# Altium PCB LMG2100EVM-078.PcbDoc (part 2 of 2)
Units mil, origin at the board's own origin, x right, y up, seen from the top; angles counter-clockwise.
Board outline 2400 x 2700 mil, 4 copper layers (Top Layer, MidLayer1, MidLayer2, Bottom Layer), stack 61.2 mil thick; 76 components, 27 nets, 153 pads, 244 vias.
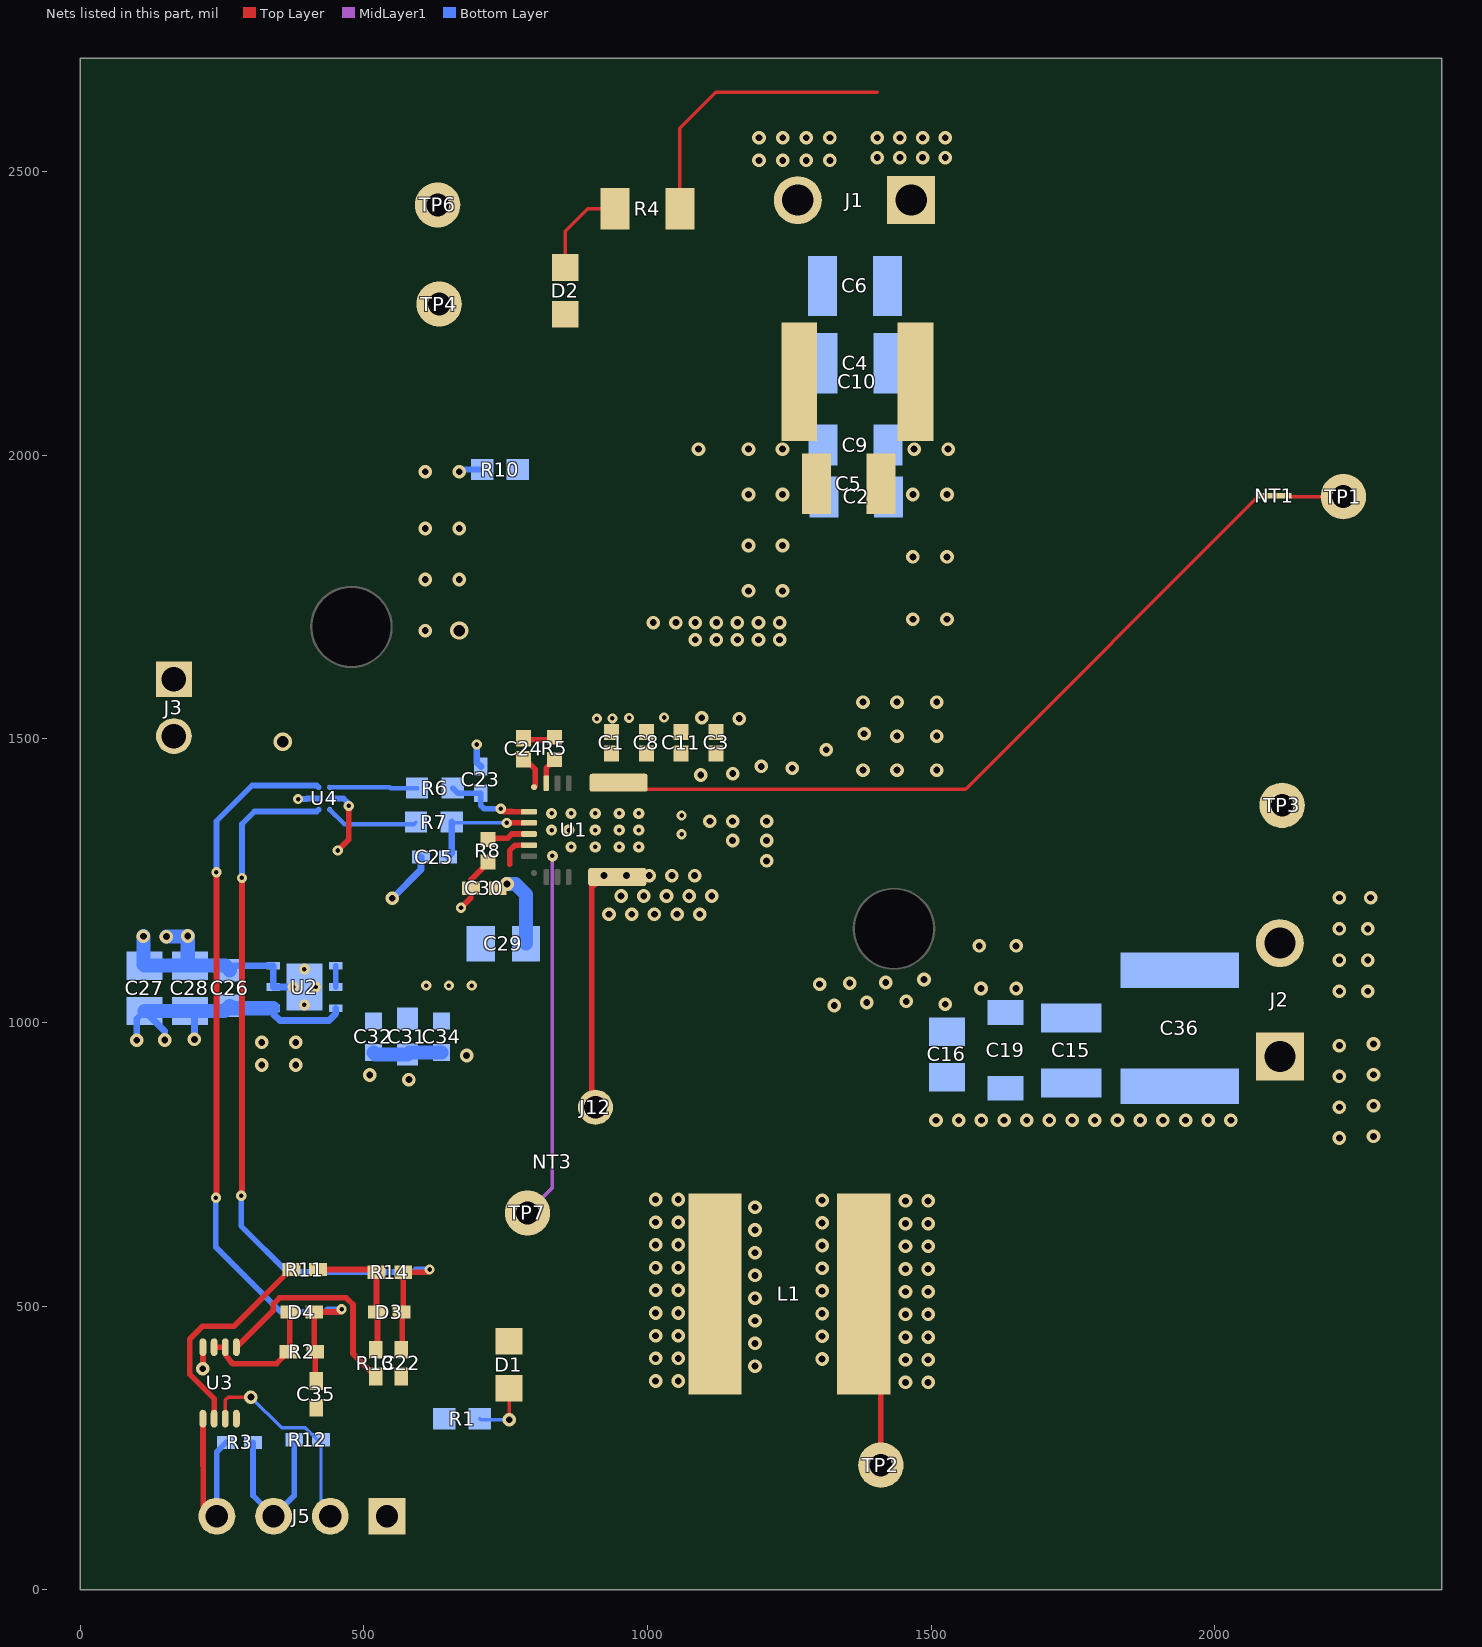
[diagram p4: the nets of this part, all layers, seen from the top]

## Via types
v1: diameter 24, hole 12, Top Layer to Bottom Layer, tented both sides, 201 vias
v2: diameter 19.68, hole 7.87, Top Layer to Bottom Layer, tented both sides, 15 vias
v3: diameter 18, hole 8, Top Layer to Bottom Layer, tented both sides, 13 vias
v4: diameter 18, hole 8, Top Layer to Bottom Layer, 9 vias
v5: diameter 19.68, hole 7.87, Top Layer to Bottom Layer, 4 vias
v6: diameter 32, hole 20, Top Layer to Bottom Layer, 2 vias

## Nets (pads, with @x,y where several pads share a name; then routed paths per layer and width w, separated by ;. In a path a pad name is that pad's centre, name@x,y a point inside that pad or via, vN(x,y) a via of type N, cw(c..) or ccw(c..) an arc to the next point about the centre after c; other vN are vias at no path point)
5V: C29.2 C30.1 C31.2 C32.1 C34.1 R1.1 R8.1 TP6.1 U2.4 U2.5 U3.8 U4.B2 | length 301.9
  Top Layer w10: v1(215.72,389.52) 216.22,390.02 U3.8@216.19,427.51 ; v4(454,1303.27) 473.23,1322.5 v4(473.23,1381.98) ; v4(671.17,1202.35) 688.67,1219.84 C30.1@688.67,1236.5 688.67,1251.62 R8.1@718.44,1281.39
  Bottom Layer w10: U4.B2@439.84,1395 455.09,1395 464,1395 473.23,1385.77 v4(473.23,1381.98) ; U2.5@450.24,1062.6 U2.4@450.24,1100
  other v3: 610,1065 650,1065 690,1065
EXT_VCC: C26.1 C27.2 C28.2 J3.1 U2.1 U2.6 | length 548.5
  Bottom Layer w12: v1(99.52,968.75) 99.52,1006.62 C27.2@113.2,1020.3 149.02,984.48 v1(149.02,969.25) ; C28.2@193.2,1020.3 201.14,1012.36 v1(201.14,970.31) ; U2.1@340,1025.2 340,1015.31 351.91,1003.4 438.33,1003.4 450.24,1015.31 U2.6@450.24,1025.2
  Bottom Layer w25: C27.2@113.2,1020.3 C28.2@193.2,1020.3 254.39,1020.3 C26.1@263.4,1029.31 267.51,1025.2 U2.1@340,1025.2
GND: C22.2 C23.1 C25.2 C26.2 C27.1 C28.1 C29.1 C30.2 C31.1 C32.2 C34.2 C35.2 D1.2 J3.2 J5.1 J5.3 R3.2 R10.2 R12.1 TP4.1 U1.15 U2.2 U2.3 U2.7 U3.4 U4.B1 | length 1268.7
  Top Layer w10: C30.2@734.73,1237.69 C30.2@735.91,1236.5 ; 757,1279 757,1303 766.64,1312.64 U1.15@791.14,1312.64
  Bottom Layer w10: R3.2@304.34,259.52 304.34,165.89 J5.3@340.72,129.52 377.1,165.89 R12.1@377.1,264.52 ; v3@390,1393.99 398.99,1393.99 400,1395 U4.B1@420.1,1395 ; v1(668,1971) 672,1975 R10.2@708.5,1975
  Bottom Layer w12: C26.2@263.4,1092.3 271.1,1100 U2.3@340,1100 U2.2@340,1062.6 v5(375.43,1062.6) ; v1(550,1219) 600.8,1269.8 C25.2@600.8,1291.8 ; v3(699,1490.2) 699,1458.6 C23.1@706.2,1451.4
  Bottom Layer w25: v1(111.2,1152.1) 111.2,1102.3 C27.1@113.2,1100.3 C28.1@193.2,1100.3 ; v1(151.8,1151.5) 188.3,1151.5 v1(189.4,1152.6) 189.4,1104.1 C28.1@193.2,1100.3 ; C26.2@263.4,1092.3 255.4,1100.3 C28.1@193.2,1100.3 ; C32.2@516.85,947 520.35,943.5 C31.1@576.78,943.5 580.28,947 C34.2@636.85,947 ; v1(752.32,1244.31) 767.22,1244.31 785.84,1225.7 C29.1@785.84,1139.06
  other v1: 579.4,899.4 510.4,907.4 320,925 380,925 681,941.8 320,965 380,965 608,1691 608,1781 668,1781 608,1871 668,1871 608,1971
  other v3: 383.86,1393.99
  other v5: 395.12,1031.1 414.8,1062.6 395.12,1094.1
  other v6: 357,1495 668,1691
HI_SIGNAL: R6.2 U4.C2 | length 154.5
  Bottom Layer w6: 545.53,1414.69 546.43,1413.78
  Bottom Layer w8: U4.C2@439.84,1414.69 545.53,1414.69 ; 546.43,1413.78 546.91,1413.3 R6.2@593.7,1413.3
K_VIN: NT1.2 TP1.1 | length 105.5
  Top Layer w6: NT1.2@2121.5,1927.26 TP1.1@2226.98,1927.26
K_VIN_GND: NT3.1 TP7.1 | length 98.5
  MidLayer1 w6: TP7.1@788.43,664.18 832.43,708.18 NT3.1@832.43,744.41
LO_SIGNAL: R7.2 U4.A2 | length 164
  Bottom Layer w6: R7.2@588.3,1349.9 R7.2@591.8,1353.4
  Bottom Layer w8: U4.A2@439.84,1375.32 465.26,1349.9 547,1349.9 R7.2@588.3,1349.9
NetC22_1: C22.1 D3.1 R14.2 U4.A1 | length 1408.9
  Top Layer w10: v4(283.6,694.4) 285,695.8 v4(285,1255) ; C22.1@565.72,423.14 567.37,424.79 567.37,489.52 569.34,491.48 R14.2@569.34,559.52 610.72,559.52 v3(615.72,564.52)
  Bottom Layer w10: v4(283.6,694.4) 283.6,641.2 364.8,560 586.72,560 591.23,564.52 v3(615.72,564.52) ; v4(285,1255) 285,1350 307,1372 416.8,1372 U4.A1@420.1,1375.3
NetC23_2: C23.2 R6.1 U1.12 | length 164.3
  Top Layer w10: v4(741.2,1376.8) 745.99,1372.01 759.98,1372.01 760.3,1371.69 U1.12@791.14,1371.69
  Bottom Layer w10: R6.1@656.7,1413.3 665.84,1404.16 C23.2@706.2,1404.16 706.2,1382.66 712.06,1376.8 v4(741.2,1376.8)
NetC24_1: C24.1 R5.1 | length 54.4
  Top Layer w10: C24.1@781.5,1498.65 835.32,1498.65 R5.1@835.7,1499.03
NetC24_2: C24.2 U1.11 | length 61.4
  Top Layer w10: C24.2@781.5,1467.15 801.97,1446.68 801.97,1416.97 U1.11@800,1415
NetC25_1: C25.1 R7.1 U1.13 | length 201.3
  Top Layer w10: v4(751.7,1352.01) U1.13@791.14,1352.01
  Bottom Layer w6: R7.1@654.8,1353.4 656.19,1352.01 v4(751.7,1352.01)
  Bottom Layer w12: C25.1@648.04,1291.8 654.8,1298.55 R7.1@654.8,1353.4
NetC35_1: C35.1 D4.1 R2.2 U4.C1 | length 1403.1
  Top Layer w10: v4(239,691.2) 240,692.2 v4(240,1265) ; C35.1@415.72,368.14 414.34,369.52 R2.2@414.34,419.52 412.37,421.48 D4.1@412.37,489.52 455.72,489.52 v3(460.72,494.52)
  Bottom Layer w10: v4(239,691.2) 239,603.8 352.8,490 431.72,490 436.23,494.52 v3(460.72,494.52) ; v4(240,1265) 240,1355 303,1418 416.8,1418 U4.C1@420.1,1414.7
NetD1_1: D1.1 R1.2 | length 108.1
  Top Layer w6: v1(756.16,299.57) D1.1@756.16,355.18
  Bottom Layer w6: R1.2@704.51,301.49 706.43,299.57 v1(756.16,299.57)
NetD2_1: D2.1 R4.2 | length 168.1
  Top Layer w6: D2.1@855,2331.34 855,2395 895,2435 R4.2@942.91,2435
NetD3_2: D3.2 R11.1 R13.2 R14.1 | length 243.4
  Top Layer w10: R11.1@419.34,564.52 517.09,564.52 R14.1@522.09,559.52 522.09,491.48 524.06,489.52 524.06,426.48 R13.2@520.72,423.14
NetD4_2: D4.2 R2.1 U3.6 U3.7 | length 217
  Top Layer w10: U3.7@235.87,427.51 U3.6@255.56,427.51 ; U3.6@256.72,413.52 268.28,398.52 346.1,398.52 R2.1@367.1,419.52 369.06,421.48 D4.2@369.06,489.52
NetJ5_2: J5.2 R12.2 U3.3 | length 371.6
  Top Layer w6: U3.3@255.56,301.52 255.62,334.42 260.72,339.52 v1@295.72,339.52
  Bottom Layer w6: v1(300.72,339.52) 354.91,285.33 396.57,285.33 417.38,264.52 R12.2@424.34,264.52 424.34,145.89 J5.2@440.72,129.52
NetJ5_4: J5.4 R3.1 U3.1 | length 307.8
  Top Layer w10: U3.1@216.19,301.52 J5.4@216.72,130.52
  Bottom Layer w10: J5.4@240.72,129.52 240.72,243.14 R3.1@257.1,259.52
NetR5_2: R5.2 U1.10 | length 51.6
  Top Layer w10: U1.10@821.65,1421.89 821.27,1422.27 821.27,1448.78 835.7,1463.21 R5.2@835.7,1467.37
NetR8_2: R8.2 U1.14 | length 75.9
  Top Layer w10: R8.2@718.44,1324.69 753.05,1324.69 760.68,1332.32 U1.14@791.14,1332.32
NetR11_2: R11.2 U3.2 | length 388.2
  Top Layer w10: U3.2@235.87,301.52 235.92,336.79 192.72,379.99 192.72,441.52 215.72,464.52 270.72,464.52 370.72,564.52 R11.2@372.09,564.52
NetR13_1: R13.1 U3.5 | length 396.5
  Top Layer w10: U3.5@275.24,427.51 340.35,492.55 340.35,503.91 350.95,514.52 469,514.52 480.72,502.8 480.72,415.89 R13.1@520.72,375.89
PGND: C1.2 C2.1 C3.2 C4.2 C5.2 C6.2 C8.2 C9.1 C10.1 C11.2 C15.2 C16.2 C19.2 C36.2 D2.2 J1.2 J2.2 NT3.2 R10.1 TP3.1 | length 533.4
  MidLayer1 w6: NT3.2@832.24,760.41 v2(832.24,1293.81)
  other v1: 1329.41,1029.99 1525.09,1032.07 1386.66,1035.19 1456.39,1037.27 2220,1055 2270,1055 1588,1060 1650,1060 1303.38,1067.45 1356.47,1069.54 1419.96,1070.59 1487.61,1075.78 2220,1110 2270,1110 1585,1135 1650,1135 2220,1165 2270,1165 2220,1220 2275,1220 1210,1285 1150,1321 1210,1321 1110,1355 1150,1355 1210,1355 1161.64,1535.87 1095.52,1537.33 1084.29,1675 1121.43,1675 1158.57,1675 1195.71,1675 1232.86,1675 1010,1705 1050,1705 1084.29,1705 1121.43,1705 1158.57,1705 1195.71,1705 1232.86,1705 1178,1761 1238,1761 1178,1841 1238,1841 1178,1931 1238,1931 1090,2011 1178,2011 1238,2011 1196.67,2520 1238.33,2520 1280,2520 1321.67,2520 1196.67,2560 1238.33,2560 1280,2560 1321.67,2560
  other v2: 865.24,1309.69 907.76,1309.69 950.28,1309.69 984.53,1309.69 830.98,1339.21 861.3,1339.21 907.76,1339.21 950.28,1339.21 984.53,1339.21 830.98,1368.74 865.24,1368.74 907.76,1368.74 950.28,1368.74 984.53,1368.74
  other v3: 1060,1332 1060,1365 910.75,1535.87 938.15,1536.09 967.66,1537.12 1029.19,1537.75
SW: J12.1 L1.1 U1.5 | length 420.2
  Top Layer w10: J12.1@908.28,850.57 901.5,857.35 901.5,1237.45 v1(923.1,1259.05)
  other v1: 1014.27,367.87 1054.27,367.87 1189.51,394.17 1014.27,407.87 1054.27,407.87 1189.51,434.17 1014.27,447.87 1054.27,447.87 1189.51,474.17 1014.27,487.87 1054.27,487.87 1189.51,514.17 1014.27,527.87 1054.27,527.87 1189.51,554.17 1014.27,567.87 1054.27,567.87 1189.51,594.17 1014.27,607.87 1054.27,607.87 1189.51,634.17 1014.27,647.87 1054.27,647.87 1189.51,674.17 1014.27,687.87 1054.27,687.87 932.15,1190.96 972.15,1190.96 1012.15,1190.96 1052.15,1190.96 1092.15,1190.96 953.44,1223 993.44,1223 1033.44,1223 1073.44,1223 1113.44,1223 963.1,1259.05 1003.1,1259.05 1043.1,1259.05 1083.1,1259.05
VIN: C1.1 C2.2 C3.1 C4.1 C5.1 C6.1 C8.1 C9.2 C10.2 C11.1 J1.1 NT1.1 R4.1 U1.7 | length 1876.1
  Top Layer w6: U1.7@949.09,1422.87 960.55,1411.42 1560.77,1411.42 2078.03,1928.68 NT1.1@2090.18,1928.68 ; R4.1@1057.09,2435 1057.09,2577.09 1120,2640 1405,2640
  other v1: 1093.81,1436.35 1150.37,1438.77 1380,1445 1440,1445 1510,1445 1255.16,1448.46 1200.71,1451.61 1315.15,1481.06 1440,1505 1510,1505 1382,1509 1380,1565 1440,1565 1510,1565 1468,1711 1528,1711 1468,1821 1528,1821 1468,1931 1528,1931 1470,2011 1530,2011 1405,2525 1445,2525 1485,2525 1525,2525 1405,2560 1445,2560 1485,2560 1525,2560
VOUT: C15.1 C16.1 C19.1 C36.1 J2.1 L1.2 TP2.1 | length 314.5
  Top Layer w6: L1.2@1381.31,521.62 L1.2@1411.4,491.53
  Top Layer w10: TP2.1@1411.4,219.57 L1.2@1411.4,491.53
  other v1: 1454.84,365.41 1494.84,365.41 1454.84,405.41 1494.84,405.41 1307.84,406.76 1454.84,445.41 1494.84,445.41 1307.84,446.76 1454.84,485.41 1494.84,485.41 1307.84,486.76 1454.84,525.42 1494.84,525.42 1307.84,526.76 1454.84,565.42 1494.84,565.42 1307.84,566.76 1454.84,605.42 1494.84,605.42 1307.84,606.76 1454.84,645.42 1494.84,645.42 1307.84,646.76 1454.84,685.42 1494.84,685.42 1307.84,686.76 2220,796.43 2280,799.29 1508.69,827.54 1548.69,827.54 1588.69,827.54 1628.69,827.54 1668.69,827.54 1708.69,827.54 1748.69,827.54 1788.69,827.54 1828.69,827.54 1868.69,827.54 1908.69,827.54 1948.69,827.54 1988.69,827.54 2028.69,827.54 2220,850.71 2280,853.57 2220,905 2280,907.86 2220,959.29 2280,962.14
pads on no net: H9.0 H10.0 H11.0 H12.0 U1.1 U1.2 U1.3 U1.4 U1.8 U1.9 U1.16

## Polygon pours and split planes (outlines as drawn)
5V on Bottom Layer "Bottom Layer-5V" (solid, pour order 63): 50,50 819.39,50 850.65,89.61 850.65,1053.22 809.27,1104.61 789.6,1104.61 804.95,1376.99 710,1463 710,2635 690,2655 50,2655 50,1028.36 50,655
PGND on Bottom Layer "Bottom Layer-No Net 8" (solid, pour order 45): 751.68,2389.2 976.97,2655.22 1341.72,2655.22 1360,2636.95 1360,1651.84 1213.12,1513.24 892.29,1513.24 751.68,1655.67
VOUT on Bottom Layer "Bottom Layer-No Net 4" (solid, pour order 64): 2350,968.17 2350,392.64 2280.19,322.83 1336.28,322.83 1280.33,378.79 1280.33,925 1836.05,925 1906.05,995 2323.16,995
SW on Bottom Layer "NONET_L-01_P-001" (solid, pour order 65): 1094.12,1273.09 1247.18,1120.03 1247.18,324.05 1205.62,282.48 941.27,282.48 896,327.75 896,786.81 951.77,827.13 951.77,882.52 896,922.02 896,1265.04 904.05,1273.08
PGND on Bottom Layer "Bottom Layer-PGND" (solid, pour order 62): 1291.09,1273.29 1306.56,1230.5 1290.55,1214.48 1290.59,1114.41 1290.55,1114.37 1290.55,950.04 1290.59,950 1290.6,950.01 1290.61,950 1807,950 1892,1035 2320,1035 2350,1065 2350,1715 1908,1715 1581,1380.59 1234.45,1380.59 1234.15,1378.55 1222.89,1378.55 820.7,1378.55 820.67,1378.58 816.4,1374.31 816.4,1295.66 820.78,1291.28 1177.2,1291.28 1195.19,1273.29
VIN on Bottom Layer "Bottom Layer-No Net 7" (solid, pour order 43): 1410,2655 1930,2655 1960,2626.17 1960,1799.67 1549.5,1408.41 897.22,1408.41 897.22,1438.4 897.22,1484.1 919.02,1484.1 1241.36,1484.1 1385.49,1628.22 1385.97,2630.97
GND on Bottom Layer "GND_L04_P031" (solid, pour order 31): 487.72,961.74 487.72,898.35 499.68,886.4 706.4,886.4 706.4,886.7 710.4,890.7 709.8,891.3 709.8,966.4 699.87,976.33 502.31,976.33 490.71,964.73
GND on Bottom Layer "Top Layer-No Net 7" (solid, pour order 42): 497.92,931.06 497.92,957.52 506.53,966.13 648.73,966.13 655.55,959.31 655.55,927.1 503.65,927.1
GND on MidLayer1 "MidLayer1-No Net 2" (solid, pour order 41): 793.92,97.97 752.39,50 68.89,50 48,70.88 48,2655 690,2655 710,2635 710,1464 774.17,1399.83 774.17,1283.7 793.92,1224.19
PGND on MidLayer1 "MidLayer1-No Net 1" (solid, pour order 60): 1336.25,322.81 1280.33,378.79 1280.33,1235.18 878.6,1235.18 843.4,1301.74 834.25,1307.58 821.16,1312.41 816.9,1316.67 816.9,1398.1 740.4,1476.96 740.4,2375.9 976.97,2655.22 2285.6,2655 2350,2596.65 2350,392.62 2280.19,322.81
SW on MidLayer1 "NONET_L-01_P-001" (solid, pour order 67): 1094.12,1273.09 1247.18,1120.03 1247.18,324.05 1205.62,282.48 941.27,282.48 896,327.75 896,786.81 951.77,827.13 951.77,882.52 896,922.02 896,1265.04 904.05,1273.08
EXT_VCC on MidLayer1 "EXT_VCC_L02_P036" (solid, pour order 36): 45.56,1667.98 51.35,1673.76 313.53,1673.76 335.25,1652.03 322.22,1639 322.22,1010.37 383.05,1010.37 395.45,997.97 404.18,949.52 412.13,905.43 412.13,839.11 395.45,822.43 383.05,804.68 380.38,807.35 68.74,804.68 34.31,839.11 34.31,1655.27 47,1667.97
GND on Top Layer "Top Layer-No Net 9" (solid, pour order 49): 33.04,1004.95 33.98,1005.89 33.98,1042.91 298.55,1042.91 301.31,1045.67 300.29,1046.68 300.29,1061.89 355.8,1061.89 365.2,1071.29 365.2,1101.97 425.04,1101.97 430.24,1096.77 430.24,1035.34 497.83,1035.34 555.25,1092.75 555.25,1104.61 695.55,1104.61 722.5,1077.66 830.17,1077.66 850.65,1053.22 850.65,89.61 819.39,50 33.04,50
PGND on Top Layer "Top Layer-No Net 2" (solid, pour order 27): 2350,1816.71 2007.3,1816.71 1569.18,1378.58 820.67,1378.58 816.68,1295.38 869.38,1299.51 870.48,1299.55 1103.1,1299.51 1290,1115 1290.59,1114.41 1290.59,950 1807,950 1892,1035 2350,1035 2320,1035 2350,1065
PGND on Top Layer "Top Layer-No Net 1" (solid, pour order 28): 751.68,2389.21 976.97,2655.22 1341.72,2655.22 1360,2636.51 1360,1651.84 1213.47,1513.25 892.11,1513.25 751.68,1656.09
SW on Top Layer "NONET_L-01_P-001" (solid, pour order 66): 1094.12,1273.09 1247.18,1120.03 1247.18,324.05 1205.62,282.48 941.27,282.48 896,327.75 896,786.81 951.77,827.13 951.77,882.52 920.11,904.94 920.11,1239.58 904.05,1273.08
VOUT on Top Layer "Bottom Layer-No Net 4" (solid, pour order 70): 2350,968.17 2350,392.64 2280.19,322.83 1336.28,322.83 1280.33,378.79 1280.33,925 1836.05,925 1906.05,995 2323.16,995
GND on Top Layer "Top Layer-No Net 10" (solid, pour order 32): 30,1065 289.13,1065 309.13,1085 309.13,1088.33 448.99,1088.33 489.82,1129.16 489.82,1174.82 500,1185 775.63,1185 792.26,1201.64 790.51,1378.58 712,1463 710,1463 710,2635 690,2655 30,2655
EXT_VCC on Top Layer "Top Layer-No Net 8" (solid, remove dead copper, pour order 50): 30,1065 289.13,1065 309.13,1088.33 340,1088.33 340,1100 350,1111.67 410,1111.67 420,1100 420,1088.33 450.87,1088.33 450,1089.34 450,1158.33 450,1170 420,1205 310,1205 300,1205 270,1240 180,1345 30,1345
5V on Top Layer "Top Layer-No Net 5" (solid, pour order 44): 420,1035.34 497.83,1035.34 500,1037.85 557.83,1105 560,1105 710,1105 720,1093.39 720,1081.78 720,1058.56 730,1046.95 730,1023.73 730,965.88 726.12,961.38 725.63,960.81 436.5,960.81
VIN on Top Layer "Top Layer-No Net" (solid, pour order 29): 1410,2655 1385.97,2630.97 1385.97,1628.22 1241.84,1484.1 897.22,1484.1 897.22,1479.74 897.22,1419.29 1552.41,1419.29 1960,1826.88 1960,2626.17 1930,2655
GND on MidLayer2 "AGND_PLANE" (solid, remove dead copper, pour order 55): 36,2651 40.04,2646.96 40.04,50 819.39,50 850.65,89.61 850.65,1223.27 804.95,1258.04 804.95,1376.99 712,1463 710,1465 710,2635 690,2655 48,2655
PGND on MidLayer2 "MidLayer1-No Net 1" (solid, pour order 71): 1336.25,322.81 1280.33,378.79 1280.33,1235.18 878.6,1235.18 816.9,1286.35 816.9,1398.1 740.4,1476.96 740.4,2375.9 976.97,2655.22 2285.6,2655 2350,2596.65 2350,392.62 2280.19,322.81
SW on MidLayer2 "NONET_L-01_P-001" (solid, pour order 68): 1094.12,1273.09 1247.18,1120.03 1247.18,324.05 1205.62,282.48 941.27,282.48 896,327.75 896,786.81 951.77,827.13 951.77,882.52 896,922.02 896,1265.04 904.05,1273.08
EXT_VCC on MidLayer2 "EXT_VCC_L03_P053" (solid, pour order 53): 29.19,1640.99 55.52,1667.32 55.52,1669.93 275.48,1669.93 304.14,1641.28 304.14,949.14 303.99,949.14 289.04,934.19 50.23,934.19 33.21,951.21 34.31,952.31 34.31,1652.28

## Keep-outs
Keep-Out Layer:
  text ".Layer_Name" at -323,-853.49 h60

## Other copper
Top Layer:
  text ".Layer_Name" at -323,-853.49 h60
Bottom Layer:
  text ".Layer_Name" at -323,-853.49 h60

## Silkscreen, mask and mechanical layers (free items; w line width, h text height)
Top Overlay:
  region: 2311,283 2000,283 2000,177 2311,177
  lines w10: 351.5,775.8 354,773.3 1709.2,773.3 1711.7,775.8 1711.7,1829.3 1706.6,1834.4 351.5,1834.4 351.5,775.8
  text "-" at 1045,2525 h80
  text "+" at 1615,2500 h80
  text "5V" at 476.43,2429.95 h40
  text "GND" at 452.99,2245.1 h40
  text "'.PRJ_Title'" at 96.77,2127.68 h42 r90
  text "Danger High" at 1579,2124 h72 r359.68
  text "Voltage" at 1716,2026 h72 r359.48
  text "GaN Evaluation Board" at 139,1902 h40
  text "VIN Sense+" at 1963,1808 h40
  text "EXTVCC" at 47.53,1780.05 h40
  text "5.5-10V" at 47.53,1718.52 h40
  text "GND" at 651,1719 h16
  text "GND" at 340,1523 h16
  text "GND" at 111.47,1381.88 h40
  text "PGND" at 1223,1374 h20
  text "-" at 2204.5,1253 h80 r90
  text "+" at 2134.2,744.6 h80
  text "VIN Sense-" at 340.77,679.62 h40
  text "IOUT 10A MAX" at 1794,588 h40
  text "Rev '.PCB_Rev'" at 2051,117 h40
  text "PWM I/P (HI)" at 824.49,79.44 h40 r90
  text "GND" at 874.53,79.17 h40 r90.25
  text "GND (LI)" at 930.73,78.79 h40 r90
  text "GND" at 988.77,79.42 h40 r90
  text "'.PRJ_Number'" at 1619.57,53.3 h40
  text ".Layer_Name" at -323,-853.49 h60
Bottom Overlay:
  text "UL 94V-0" at 2306,1647 h48
  text "Caution" at 2240.5,1562.1 h72 r359.68
  text "Hot Surface" at 2336.1,1466.5 h72 r359.68
  text ".Layer_Name" at -323,-853.49 h60
Top Paste:
  text ".Layer_Name" at -323,-853.49 h60
Bottom Paste:
  text ".Layer_Name" at -323,-853.49 h60
Top Solder:
  text ".Layer_Name" at -323,-853.49 h60
  text ".Layer_Name" at -323,-853.49 h60
Bottom Solder:
  text ".Layer_Name" at -323,-853.49 h60
Drill Guide:
  text ".Layer_Name" at -323,-853.49 h60
M1 Board Outline:
  lines w25: 5,0 5,2700 2400,2700 2400,0 5,0
  text ".Layer_Name" at -323,-853.49 h60
M2 Board Dimensions:
  rectangle: -775.5,-405.5 -400.5,-280.5
  rectangle: -900.5,-280.5 -775.5,-155.5
  lines w7: -900.5,-280.5 99.5,-280.5 ; -775.5,-405.5 -775.5,-155.5 ; -650.5,-405.5 -650.5,-155.5 ; -400.5,-405.5 -400.5,-155.5 ; -150.5,-405.5 -150.5,-155.5 ; -900.5,-405.5 -900.5,-155.5 99.5,-155.5 99.5,-405.5 -900.5,-405.5
  lines w10: -900.5,-470.5 -900.5,-450.5 ; -840.5,-480.5 -900.5,-460.5 ; -840.5,-440.5 -900.5,-460.5 ; -676.42,-460.5 -900.5,-460.5 ; -124.58,-460.5 99.5,-460.5 ; 39.5,-480.5 99.5,-460.5 ; 39.5,-440.5 99.5,-460.5 ; 99.5,-470.5 99.5,-450.5
  text "1000 (mil)" at -666.42,-496.49 h60
  text ".Layer_Name" at -323,-853.49 h60
M3 3D STEP Top:
  text ".Layer_Name" at -323,-853.49 h60
M4 3D STEP Bottom:
  text ".Layer_Name" at -323,-853.49 h60
M5 Assembly Top:
  lines w10: -1192,-925.17 5408,-925.17 ; -1192,-721.83 5410,-721.83 ; -1192,-518.5 -1192,-1128.5 2813,-1128.5 5410,-1128.5 5410,-518.5 -1191.5,-518.5 -1191.5,-1128.5 384,-1128.5 ; 1273,-1128.5 1273,-518.5 ; 2540,-721.83 2540,-518.5 ; 3380,-721.83 3380,-518.5 ; 4002,-1135 4002,-932.17
  text "COMPONENTS MARKED 'DNP' SHOULD NOT BE POPULATED." at 253.5,-313.5 h60
  text "ASSEMBLY VARIANT:" at 253,-429 h60
  text ".VariantName" at 1289,-429 h60
  text "PCB VIEWED FROM TOP SIDE" at -1128.5,-650.67 h60
  text "BOARD #:" at 1348,-650.67 h60
  text ".PRJ_Number" at 1893.5,-650.67 h60
  text "REV:" at 2738,-650.67 h60
  text ".PCB_Rev" at 3029.5,-650.67 h60
  text "SVN REV:" at 3576,-650.67 h60
  text ".VersionControl_RevNumber" at 4082,-650.67 h60
  text "IGNORE ->" at -1128.5,-853.49 h60
  text "PLOT NAME =" at -1128.5,-1059.33 h60
  text ".plot_File_Name" at -323,-1059.33 h60
  text "GENERATED    :" at 1350,-1059.33 h60
  text ".Print_Date" at 2219.5,-1059.33 h60
  text ".Print_Time" at 2948.5,-1059.33 h60
  text "TEXAS INSTRUMENTS" at 4213,-1059.33 h60
M6 Assembly Bottom:
  lines w10: -1192.5,-722.33 5409.5,-722.33 ; -1190.5,-925.67 5409.5,-925.67 ; 215.5,-1135.5 215.5,-932.67 ; 837.5,-722.33 837.5,-519 ; 1677.5,-722.33 1677.5,-519 ; 2944.5,-1129 2944.5,-519 ; 3833.5,-1129 5409,-1129 5409,-519 -1192.5,-519 -1192.5,-1129 1404.5,-1129 5409.5,-1129 5409.5,-519
  text "COMPONENTS MARKED 'DNP' SHOULD NOT BE POPULATED." at 5202,-313 h60
  text ".VariantName" at 4158,-429 h60
  text "ASSEMBLY VARIANT:" at 5197,-429 h60
  text ".VersionControl_RevNumber" at 135.5,-651.17 h60
  text "SVN REV:" at 641.5,-651.17 h60
  text ".PCB_Rev" at 1188,-651.17 h60
  text "REV:" at 1479.5,-651.17 h60
  text ".PRJ_Number" at 2324,-651.17 h60
  text "BOARD #:" at 2869.5,-651.17 h60
  text "PCB VIEWED FROM BOTTOM SIDE" at 5346,-651.17 h60
  text "IGNORE ->" at 1647.85,-853.49 h60
  text "TEXAS INSTRUMENTS" at 4.5,-1059.83 h60
  text ".Print_Time" at 1269,-1059.83 h60
  text ".Print_Date" at 1998,-1059.83 h60
  text "GENERATED    :" at 2867.5,-1059.83 h60
  text ".plot_File_Name" at 4540.5,-1059.83 h60
  text "PLOT NAME =" at 5346,-1059.83 h60
M9 Title Sheet:
  drawing of 56 lines, arcs and shapes, not listed
  text "1" at -160.16,8041.5 h70
  text "2" at 2335.5,8041.5 h70
  text "3" at 4824.84,8041.5 h70
  text "4" at 7331.51,8041.5 h70
  text "5" at 9830.5,8041.5 h70
  text "A" at -1316.5,6898.5 h70
  text "A" at 13483.5,6898.5 h70
  text "B" at -1316.5,4518.5 h70
  text "B" at 13483.5,4518.5 h70
  text "C" at -1316.5,2143.5 h70
  text "C" at 13483.5,2143.5 h70
  text "PROJECT TITLE:" at 10443.5,282.5 h45
  text ".PRJ_Title" at 10493.5,149.17 h70
  text "DESIGNED FOR:" at 10443.5,-18.5 h45
  text ".PRJ_Customer" at 10493.5,-158.5 h70
  text "D" at -1316.5,-226.5 h70
  text "D" at 13483.5,-226.5 h70
  text "FILE NAME:" at 10443.5,-318.5 h45
  text ".PCB_File_Name_No_Path" at 10493.5,-438.5 h70
  text "Texas Instruments (TI) and/or its licensors do not warrant the accuracy or completeness of this specification" at 5474,-600.34 h45
  text "ENGINEER:" at 10443.5,-608.5 h45
  text "LAYOUT BY:" at 11948.5,-608.5 h45
  text "or any information contained therein. TI and/or its licensors do not warrant that this design will meet" at 5429.01,-713 h45
  text ".PRJ_Engineer" at 10493.5,-763.49 h70
  text ".PRJ_Engineer" at 11999,-763.49 h70
  text "the specifications, will be suitable for your application or fit for any particular purpose, or will operate in" at 5429.01,-825.67 h45
  text ".Layer_Name" at -323,-853.49 h60
  text "ALTIUM DESIGNER VERSION:" at 11948.5,-918.5 h45
  text "an implementation. TI and/or its licensors do not warrant that the design is production worthy. You should" at 5429.01,-938.33 h45
  text "completely validate and test your design implementation to confirm the system functionality for your application." at 5474,-1051 h45
  text ".print_Scale" at 10493.5,-1051.83 h70
  text ".Application_BuildNumber" at 11999,-1051.83 h70
  text "1" at -160.16,-1258.5 h70
  text "2" at 2335.5,-1258.5 h70
  text "3" at 4824.84,-1258.5 h70
  text "4" at 7331.51,-1258.5 h70
  text "5" at 9830.5,-1258.5 h70
  text "6" at 12335.5,-1258.5 h70
M10 Fab Notes:
  drawing of 212 lines, arcs and shapes, not listed
  text "DESIGN INFORMATION" at 11481.02,6815 h60
  text "(REFER ALSO ARRAY/PANEL PROFILING INFORMATION)" at 11119.46,6653.29 h60
  text "BOARD SIZE" at 10433.46,6649 h60
  text "2400MIL" at 10895.78,6521.18 h60
  text "X" at 11401.46,6521.18 h60
  text "2700" at 11632.78,6521.18 h60
  text "Number of Layers :" at 10836.46,6324 h60
  text "4" at 11931.27,6314 h60
  text "MIN. TRACK WIDTH:" at 10836.46,6185 h60
  text "6" at 11932.7,6185 h60
  text "MIL" at 12087.46,6185 h60
  text "MIN. CLEARANCE:" at 10836.46,6053 h60
  text "6" at 11932.7,6053 h60
  text "MIL" at 12087.46,6053 h60
  text "MIN. VIA PAD SIZE:" at 10836.46,5921 h60
  text "18" at 11902.71,5921 h60
  text "MIL" at 12087.46,5921 h60
  text "0.05mm (2MIL)" at 11531.46,5779.29 h60
  text "MINIMUM ANNULAR RING" at 10507.23,5775.01 h60
  text "EXTERNAL" at 12239.46,5775.01 h60
  text "PER" at 10707.23,5657 h60
  text "IPC-D-275 CLASS 2 LEVEL C" at 10927.23,5657 h60
  text "MIL, HOLES" at 12415.46,5544.71 h60
  text "+/-" at 12023,5544 h60
  text "+/-" at 12877,5544 h60
  text "REGISTRATION TOLERANCES:" at 10507.23,5539 h60
  text "METAL" at 11707,5539 h60
  text "5" at 12283.2,5539 h60
  text "3" at 13116.2,5539 h60
  text "MIL" at 13232.46,5539 h60
  text "MATERIAL:" at 10432.46,5329.54 h60
  text "FR-4 High Tg" at 11418.9,5189.21 h60
  text "FR-408" at 10853.46,5180.64 h60
  text "X" at 11265.46,5180.64 h60
  text "OTHER" at 12341.46,5180.64 h60
  text "62 MIL (1.6mm) +/-10%" at 11173.56,5017.92 h60
  text "THICKNESS:" at 10507.23,5013.64 h60
  text "X" at 11045.4,5013.64 h60
  text "OTHER" at 12458.46,5013.64 h60
  text "TOLERANCE:" at 10507.23,4855.64 h60
  text "X" at 11346.53,4855.64 h60
  text "ANSI IPC-6012 TYPE 3 CLASS 2" at 11533.48,4855.64 h60
  text "OTHER +/-" at 11533.46,4699.64 h60
  text "BOW & TWIST:" at 10507.23,4542.64 h60
  text "X" at 11346.53,4542.64 h60
  text "ANSI IPC-6012 TYPE 3 CLASS 2" at 11533.48,4542.64 h60
  text "OTHER +/-" at 11533.46,4384.13 h60
  text "COPPER THICKNESS (FINISHED):" at 10432.46,4248.64 h60
  text "1.4MIL (1oz)" at 11312.46,4095.92 h60
  text "2MIL (1.4oz)" at 12079.46,4095.92 h60
  text "2.8MIL (2oz)" at 12806.46,4095.92 h60
  text "OUTER:" at 10789.46,4091.64 h60
  text "X" at 12700,4085 h60
  text "X" at 11950,3955 h60
  text "1.4MIL (1oz)" at 11312.46,3938.92 h60
  text "2.8MIL (2oz)" at 12079.46,3938.92 h60
  text "N/A" at 12806,3939.29 h60
  text "INNER SIGNAL:" at 10500.38,3934.64 h60
  text "DRILLING:" at 10432.46,3795.64 h60
  text "REFERENCE:" at 10507.23,3678.64 h60
  text "X" at 11155.46,3678.64 h60
  text "AS SHOWN" at 11342.46,3678.64 h60
  text "X" at 12056.46,3678.64 h60
  text "NC_DRILL FILES" at 12193.46,3678.64 h60
  text "PTH MIN COPPER THICKNESS:" at 10507.23,3520.64 h60
  text "X" at 11857.46,3520.64 h60
  text "1MIL" at 11994.46,3520.64 h60
  text "OTHER" at 12491.46,3520.64 h60
  text "BOARD FINISH:" at 10432.46,3361.64 h60
  text "SILKSCREEN:" at 10587.68,3243.64 h60
  text "X" at 11536.46,3243.64 h60
  text "TOP" at 11662.46,3243.64 h60
  text "X" at 12046.46,3243.64 h60
  text "BOTTOM" at 12173.46,3243.64 h60
  text "SILKSCREEN COLOR:" at 10587.68,3076.64 h60
  text "X" at 11535.42,3076.64 h60
  text "WHITE" at 11662.46,3076.64 h60
  text "OTHER" at 12173.46,3076.64 h60
  text "SOLDER RESIST COLOR:" at 10587.68,2906.64 h60
  text "X" at 11155.42,2747.44 h60
  text "GREEN" at 11282.46,2747.44 h60
  text "BLUE" at 11873.46,2747.44 h60
  text "OTHER" at 12411.46,2747.44 h60
  text "IMMERSION GOLD (ENIG)" at 11493.46,2558.92 h60
  text "ENEPIG" at 12831,2555.64 h60
  text "SURFACE FINISH:" at 10432.46,2554.64 h60
  text "X" at 11306.51,2554.64 h60
  text "IMM. TIN/SILVER OR EQUIV" at 10762,2397.64 h60
  text "OTHER" at 12193.46,2397.64 h60
  text "ARRAY/PANEL:" at 10432.46,2218.64 h60
  text "CUT AND TRIM PER MECH LAYER 1" at 11493.46,2214.35 h60
  text "N.C. ROUTE" at 11493.46,2062.64 h60
  text "X" at 12172.46,2062.64 h60
  text "V. SCORE" at 12359.46,2062.64 h60
  text "CERTIFICATION:" at 10432.46,1925.64 h60
  text "MATERIALS AND WORKMANSHIP FOR ALL PCBS" at 11157.46,1925.64 h60
  text "TO MEET OR EXCEED THE REQUIREMENTS OF:" at 11157.46,1827.64 h60
  text "X" at 10783.96,1691.14 h60
  text "ANSI IPC-A-600F CLASS ->" at 10922.96,1691.14 h60
  text "X" at 12562.02,1691.14 h60
  text "2" at 12680.96,1691.14 h60
  text "1" at 12365.96,1689.64 h60
  text "3" at 13034.96,1689.64 h60
  text "X" at 10786.02,1531.64 h60
  text "UL 94V-0" at 10922.96,1531.64 h60
  text "X" at 11598.02,1531.64 h60
  text "RoHS" at 11734.96,1531.64 h60
  text "OTHER" at 12379.36,1531.64 h60
  text "PER ORDER" at 12776.42,1531.64 h60
  text "ADDITIONAL REQUIREMENTS:" at 10432.46,1390.64 h60
  text "MICROSECTION:" at 10507.23,1275.64 h60
  text "YES" at 11412.96,1275.64 h60
  text "REQUIRED" at 12274.46,1119.5 h60
  text "BARE BOARD ELEC. TEST:" at 10507.23,1116.64 h60
  text "NONE" at 11812.96,1116.64 h60
  text "X" at 12147.46,1116.64 h60
  text "PER ORDER" at 12866.46,1116.64 h60
  text "MANUFACTURER'S UL:" at 10507.23,959.64 h60
  text "RAIL" at 11672.96,955.35 h60
  text "METAL" at 12164.77,955.35 h60
  text "X" at 12540,955 h60
  text "SILK" at 12676.46,955.35 h60
  text ".Layer_Name" at -323,-853.49 h60
M11 Gerber Information:
  lines w10: -1192,-925.17 5408,-925.17 ; -1192,-721.83 5410,-721.83 ; -1192,-518.5 -1192,-1128.5 2813,-1128.5 5410,-1128.5 5410,-518.5 -1191.5,-518.5 -1191.5,-1128.5 384,-1128.5 ; 1273,-1128.5 1273,-518.5 ; 2540,-721.83 2540,-518.5 ; 3380,-721.83 3380,-518.5 ; 4002,-1135 4002,-932.17
  text "ALL ARTWORK VIEWED FROM TOP SIDE" at -1128.5,-650.67 h60
  text "BOARD #:" at 1348,-650.67 h60
  text ".PRJ_Number" at 1893.5,-650.67 h60
  text "REV:" at 2738,-650.67 h60
  text ".PCB_Rev" at 3029.5,-650.67 h60
  text "SVN REV:" at 3576,-650.67 h60
  text ".VersionControl_RevNumber" at 4082,-650.67 h60
  text "LAYER NAME =" at -1128.5,-853.49 h60
  text "PLOT NAME =" at -1128.5,-1059.33 h60
  text ".plot_File_Name" at -323,-1059.33 h60
  text "GENERATED    :" at 1350,-1059.33 h60
  text ".Print_Date" at 2219.5,-1059.33 h60
  text ".Print_Time" at 2948.5,-1059.33 h60
  text "TEXAS INSTRUMENTS" at 4213,-1059.33 h60
M12 Stackup:
  drawing of 295 lines, arcs and shapes, not listed
  text "Layer" at 5672.34,6831 h60
  text "Name" at 6082.26,6831 h60
  text "Material" at 7012,6831 h60
  text "Thickness" at 7871.77,6831 h60
  text "Constant" at 8521.6,6831 h60
  text "Board Layer Stack" at 9091.46,6831 h60
  text "Top Overlay" at 6082.26,6711 h60
  text "Top Solder" at 6082.26,6591 h60
  text "Solder Resist" at 7012,6591 h60
  text "0.40mil" at 7871.77,6591 h60
  text "3.5" at 8521.6,6591 h60
  text "1" at 5672.34,6471 h60
  text "Top Layer" at 6082.26,6471 h60
  text "2.80mil" at 7871.77,6471 h60
  text "Dielectric1" at 6082.26,6351 h60
  text "FR-4" at 7012,6351 h60
  text "5.00mil" at 7871.77,6351 h60
  text "4.8" at 8521.6,6351 h60
  text "2" at 5672.34,6231 h60
  text "MidLayer1" at 6082.26,6231 h60
  text "2.80mil" at 7871.77,6231 h60
  text "Dielectric2" at 6082.26,6111 h60
  text "FR-4" at 7012,6111 h60
  text "40.00mil" at 7871.77,6111 h60
  text "4.8" at 8521.6,6111 h60
  text "3" at 5672.34,5991 h60
  text "MidLayer2" at 6082.26,5991 h60
  text "2.80mil" at 7871.77,5991 h60
  text "Dielectric3" at 6082.26,5871 h60
  text "FR-4" at 7012,5871 h60
  text "5.00mil" at 7871.77,5871 h60
  text "4.2" at 8521.6,5871 h60
  text "4" at 5672.34,5751 h60
  text "Bottom Layer" at 6082.26,5751 h60
  text "2.80mil" at 7871.77,5751 h60
  text "Bottom Solder" at 6082.26,5631 h60
  text "Solder Resist" at 7012,5631 h60
  text "0.40mil" at 7871.77,5631 h60
  text "3.5" at 8521.6,5631 h60
  text "Bottom Overlay" at 6082.26,5511 h60
  text ".Layer_Name" at -323,-853.49 h60
M13 Component Bodies Top:
  text ".Layer_Name" at -323,-853.49 h60
M14 Component Bodies Bottom:
  text ".Layer_Name" at -323,-853.49 h60
M15 Courtyards Top:
  text ".Layer_Name" at -323,-853.49 h60
M16 Courtyards Bottom:
  text ".Layer_Name" at -323,-853.49 h60
Drill Drawing:
  circle w10: c5680.72,4651.32 r27.63
  circle w10: c5680.72,4029.72 r16.58
  circle w10: c5680.72,4029.72 r27.63
  lines w10: 5653.09,3891.59 5666.9,3891.59 5680.72,3877.78 5694.53,3891.59 5708.34,3891.59 5694.53,3905.4 5708.34,3919.22 5694.53,3919.22 5680.72,3933.03 5666.9,3919.22 5653.09,3919.22 5666.9,3905.4 5653.09,3891.59 ; 5653.09,4126.42 5680.72,4140.23 5708.34,4126.42 5694.53,4154.04 5708.34,4181.67 5680.72,4167.86 5653.09,4181.67 5666.9,4154.04 5653.09,4126.42 ; 5653.09,4250.74 5708.34,4250.74 5708.34,4305.99 5653.09,4305.99 5653.09,4250.74 ; 5653.09,4430.31 5708.34,4430.31 5680.72,4375.06 5653.09,4430.31 ; 5653.09,4499.38 5680.72,4513.19 5708.34,4499.38 5694.53,4527 5708.34,4554.63 5680.72,4540.82 5653.09,4554.63 5666.9,4527 5653.09,4499.38 ; 5653.09,4872.34 5653.09,4886.15 5666.9,4899.96 5653.09,4913.78 5653.09,4927.59 5666.9,4927.59 5680.72,4913.78 5694.53,4927.59 5708.34,4927.59 5708.34,4913.78 5694.53,4899.96 5708.34,4886.15 5708.34,4872.34 5694.53,4872.34 5680.72,4886.15 5666.9,4872.34 5653.09,4872.34 ; 5664.14,4419.26 5697.29,4419.26 5680.72,4386.11 5664.14,4419.26 ; 5664.14,4510.43 5680.72,4518.71 5697.29,4510.43 5689.01,4527 5697.29,4543.58 5680.72,4535.29 5664.14,4543.58 5672.43,4527 5664.14,4510.43 ; 5664.14,4883.39 5664.14,4891.67 5672.43,4899.96 5664.14,4908.25 5664.14,4916.54 5672.43,4916.54 5680.72,4908.25 5689.01,4916.54 5697.29,4916.54 5697.29,4908.25 5689.01,4899.96 5697.29,4891.67 5697.29,4883.39 5689.01,4883.39 5680.72,4891.67 5672.43,4883.39 5664.14,4883.39
  lines w12: 5603,3840.48 8834.49,3840.48 ; 5603,5083.68 8834.49,5083.68 ; 5940.86,3716.16 5940.86,5208 ; 6272.86,3716.16 6272.86,5208 ; 6909.43,3716.16 6909.43,5208 ; 7168.57,3716.16 7168.57,5208 ; 7543.72,3716.16 7543.72,5208 ; 8268.05,3716.16 8268.05,5208 ; 5603,3716.16 8834.49,3716.16 8834.49,5208 5603,5208 5603,3716.16
  text "Symbol" at 5677.59,5120.98 h72
  text "Quantity" at 5978.16,5120.98 h72
  text "Finished Hole Size" at 6310.16,5120.98 h72
  text "Plated" at 6946.72,5120.98 h72
  text "Hole Type" at 7205.86,5120.98 h72
  text "Drill Layer Pair" at 7581.02,5120.98 h72
  text "Hole Tolerance" at 8305.35,5120.98 h72
  text "19" at 5978.16,4996.66 h60
  text "7.87mil (0.200mm)" at 6310.16,4996.66 h60
  text "PTH" at 6946.72,4996.66 h60
  text "Round" at 7205.86,4996.66 h60
  text "Top Layer - Bottom Layer" at 7581.02,4996.66 h60
  text "C" at 5652.31,4986.66 h55.25
  text "22" at 5978.16,4872.34 h60
  text "8.00mil (0.203mm)" at 6310.16,4872.34 h60
  text "PTH" at 6946.72,4872.34 h60
  text "Round" at 7205.86,4872.34 h60
  text "Top Layer - Bottom Layer" at 7581.02,4872.34 h60
  text "201" at 5978.16,4748.02 h60
  text "12.00mil (0.305mm)" at 6310.16,4748.02 h60
  text "PTH" at 6946.72,4748.02 h60
  text "Round" at 7205.86,4748.02 h60
  text "Top Layer - Bottom Layer" at 7581.02,4748.02 h60
  text "A" at 5652.31,4738.03 h55.25
  text "2" at 5978.16,4623.7 h60
  text "20.00mil (0.508mm)" at 6310.16,4623.7 h60
  text "PTH" at 6946.72,4623.7 h60
  text "Round" at 7205.86,4623.7 h60
  text "Top Layer - Bottom Layer" at 7581.02,4623.7 h60
  text "4" at 5978.16,4499.38 h60
  text "39.37mil (1.000mm)" at 6310.16,4499.38 h60
  text "PTH" at 6946.72,4499.38 h60
  text "Round" at 7205.86,4499.38 h60
  text "Top Layer - Bottom Layer" at 7581.02,4499.38 h60
  text "6" at 5978.16,4375.06 h60
  text "40.00mil (1.016mm)" at 6310.16,4375.06 h60
  text "PTH" at 6946.72,4375.06 h60
  text "Round" at 7205.86,4375.06 h60
  text "Top Layer - Bottom Layer" at 7581.02,4375.06 h60
  text "1" at 5978.16,4250.74 h60
  text "40.16mil (1.020mm)" at 6310.16,4250.74 h60
  text "PTH" at 6946.72,4250.74 h60
  text "Round" at 7205.86,4250.74 h60
  text "Top Layer - Bottom Layer" at 7581.02,4250.74 h60
  text "2" at 5978.16,4126.42 h60
  text "43.31mil (1.100mm)" at 6310.16,4126.42 h60
  text "PTH" at 6946.72,4126.42 h60
  text "Round" at 7205.86,4126.42 h60
  text "Top Layer - Bottom Layer" at 7581.02,4126.42 h60
  text "4" at 5978.16,4002.1 h60
  text "55.12mil (1.400mm)" at 6310.16,4002.1 h60
  text "PTH" at 6946.72,4002.1 h60
  text "Round" at 7205.86,4002.1 h60
  text "Top Layer - Bottom Layer" at 7581.02,4002.1 h60
  text "2" at 5978.16,3877.78 h60
  text "137.79mil (3.500mm)" at 6310.16,3877.78 h60
  text "PTH" at 6946.72,3877.78 h60
  text "Round" at 7205.86,3877.78 h60
  text "Top Layer - Bottom Layer" at 7581.02,3877.78 h60
  text "263 Total" at 5978.16,3753.46 h60
  text ".Layer_Name" at -323,-853.49 h60

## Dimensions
-120,0 to -195,2700 on M2 Board Dimensions
0,-50 to 2400,-50 on M2 Board Dimensions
